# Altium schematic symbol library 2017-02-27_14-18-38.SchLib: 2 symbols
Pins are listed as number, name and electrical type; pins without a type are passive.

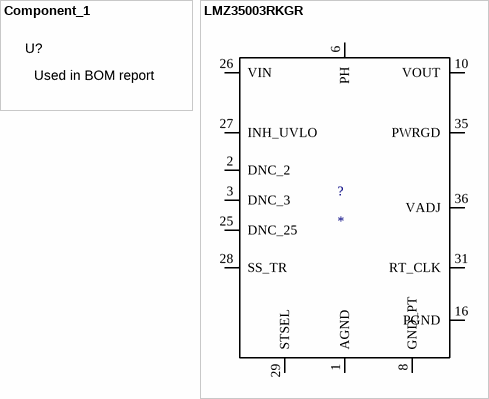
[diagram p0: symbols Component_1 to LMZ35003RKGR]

## Component_1
designator U?, comment Used in BOM report
SymbolVersion: use current date i.e. 2008-05-20; SymbolCreator: Use a-id; CompType: Used in some BOM reports.  Useful for finding later.; U/M: EA, IN, or GM

## LMZ35003RKGR
designator ?
Imported; Frequency: 1000000.0; Imax: 2.5; Mktg_Package: R-PB1QFN-N41; NSID: LMZ35003RKGR; Vendor: Texas Instruments
footprint RKG0041A
pins: 1 AGND, 2 DNC_2, 3 DNC_3, 4 AGND, 5 AGND, 6 PH, 7 PH, 8 GND_PT, 9 GND_PT, 10 VOUT, 11 VOUT, 12 VOUT, 13 VOUT, 14 VOUT, 15 VOUT, 16 PGND, 17 PGND, 18 PGND, 19 PGND, 20 PGND, 21 PH, 22 PH, 23 PH, 24 PH, 25 DNC_25, 26 VIN, 27 INH_UVLO, 28 SS_TR, 29 STSEL, 30 AGND, 31 RT_CLK, 32 AGND, 33 AGND, 34 AGND, 35 PWRGD, 36 VADJ, 37 AGND, 38 PH, 39 VOUT, 40 PGND, 41 PH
